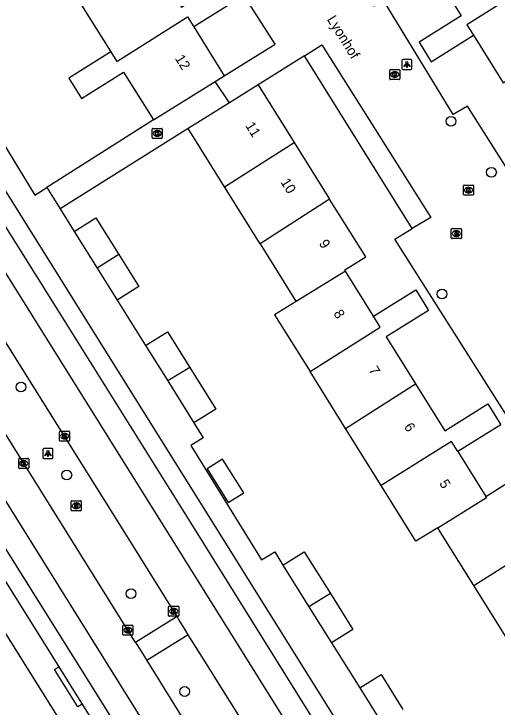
# Model space of a CAD drawing. Extents: x 158461 to 159795, y 387220 to 388672.
# Drawn here: x 158840 to 158888.2, y 387898.2 to 387967.3 of the extents above; entities that cross this region are included whole.
import ezdxf

# ---------------------------------------------------------------- set-up
doc = ezdxf.new("R2010")
doc.units = 0
for name, color, linetype in [('IMGEO_Boom', 7, 'Continuous'), ('IMGEO_Brandkraan', 7, 'Continuous'), ('IMGEO_Kolk', 7, 'Continuous'), ('IMGEO_Lichtpunt', 7, 'Continuous'), ('IMGEO_Openbare_ruimte_label', 7, 'Continuous'), ('IMGEO_Pand', 7, 'Continuous'), ('IMGEO_Pand_nummerreeks', 7, 'Continuous'), ('IMGEO_Parkeervlak_open', 7, 'Continuous'), ('IMGEO_Rijbaan_lokaal_gesloten', 7, 'Continuous'), ('IMGEO_Rijbaan_lokaal_open', 7, 'Continuous'), ('IMGEO_Rioolput', 7, 'Continuous'), ('IMGEO_Voetpad_open', 7, 'Continuous')]:
    doc.layers.add(name, color=color, linetype=linetype)

msp = doc.modelspace()

# ---------------------------------------------------------------- linework, layer by layer
at = {"layer": 'IMGEO_Boom'}
for centre in [(158883.59, 387956.588), (158887.621, 387951.512), (158882.693, 387939.38), (158840.749, 387930.117), (158845.315, 387921.36), (158851.709, 387909.538), (158857.066, 387899.781)]:
    msp.add_circle(centre, 0.489, dxfattribs=at)
at = {"layer": 'IMGEO_Brandkraan'}
for p, q in [((158883.624, 387944.978), (158883.624, 387945.83)), ((158883.699, 387945.904), (158884.551, 387945.904)), ((158884.625, 387945.83), (158884.625, 387944.978)), ((158884.135, 387945.124), (158884.11, 387945.124)), ((158884.112, 387945.684), (158884.137, 387945.684)), ((158884.551, 387944.904), (158883.699, 387944.904))]:
    msp.add_line(p, q, dxfattribs=at)
for points in [[(158883.624, 387944.978), (158883.624, 387945.83)], [(158883.699, 387945.904), (158884.551, 387945.904)], [(158884.625, 387945.83), (158884.625, 387944.978)], [(158883.972, 387945.604), (158883.972, 387945.204), (158884.185, 387945.204)], [(158884.203, 387945.604), (158883.972, 387945.604)], [(158884.151, 387945.523), (158884.097, 387945.523), (158884.097, 387945.447)], [(158884.097, 387945.447), (158884.15, 387945.447)], [(158884.159, 387945.371), (158884.097, 387945.371), (158884.097, 387945.29)], [(158884.097, 387945.29), (158884.159, 387945.29)], [(158884.551, 387944.904), (158883.699, 387944.904)]]:
    msp.add_lwpolyline(points, dxfattribs=at)
for centre, radius, start, end in [((158883.701, 387945.828), 0.0765, 91.55205, 178.44795), ((158883.701, 387945.828), 0.0765, 91.55205, 178.44795), ((158884.549, 387945.828), 0.0765, 1.55205, 88.44795), ((158884.549, 387945.828), 0.0765, 1.55205, 88.44795), ((158884.152, 387945.485), 0.0379, 267.82845, 90.93552), ((158884.16, 387945.33), 0.0404, 269.87594, 90.50774), ((158884.191, 387945.455), 0.251, 268.66757, 293.53466), ((158884.207, 387945.459), 0.145, 59.4692, 91.53667), ((158884.232, 387945.506), 0.0922, 285.51372, 58.15012), ((158884.237, 387945.314), 0.105, 301.31148, 78.98903), ((158883.701, 387944.98), 0.0765, 181.55205, 268.44795), ((158883.701, 387944.98), 0.0765, 181.55205, 268.44795), ((158884.549, 387944.98), 0.0765, 271.55205, 358.44795), ((158884.549, 387944.98), 0.0765, 271.55205, 358.44795)]:
    msp.add_arc(centre, radius, start, end, dxfattribs=at)
for centre, major_axis, ratio, start_param, end_param in [((158884.111, 387945.404), (-0.387, 0.002), 0.722429, 4.712389, 7.853982), ((158884.136, 387945.404), (-0.39, 0.002), 0.717154, 1.570796, 4.712389)]:
    msp.add_ellipse(centre, major_axis=major_axis, ratio=ratio, start_param=start_param, end_param=end_param, dxfattribs=at)
at = {"layer": 'IMGEO_Kolk'}
for p, q in [((158877.492, 387960.822), (158877.492, 387961.674)), ((158877.567, 387961.748), (158878.419, 387961.748)), ((158878.493, 387961.674), (158878.493, 387960.822)), ((158878.003, 387960.968), (158877.978, 387960.968)), ((158877.98, 387961.528), (158878.005, 387961.528)), ((158878.419, 387960.748), (158877.567, 387960.748)), ((158853.829, 387954.962), (158853.829, 387955.814)), ((158853.904, 387955.888), (158854.756, 387955.888)), ((158854.317, 387955.668), (158854.342, 387955.668)), ((158854.83, 387955.814), (158854.83, 387954.962)), ((158854.756, 387954.888), (158853.904, 387954.888)), ((158854.34, 387955.108), (158854.315, 387955.108)), ((158884.836, 387949.308), (158884.836, 387950.16)), ((158884.911, 387950.234), (158885.763, 387950.234)), ((158885.324, 387950.014), (158885.349, 387950.014)), ((158885.837, 387950.16), (158885.837, 387949.308)), ((158885.763, 387949.234), (158884.911, 387949.234)), ((158885.347, 387949.454), (158885.322, 387949.454)), ((158844.671, 387925.722), (158845.523, 387925.722)), ((158844.596, 387924.796), (158844.596, 387925.648)), ((158845.084, 387925.502), (158845.109, 387925.502)), ((158845.597, 387925.648), (158845.597, 387924.796)), ((158845.523, 387924.722), (158844.671, 387924.722)), ((158845.107, 387924.942), (158845.082, 387924.942)), ((158840.526, 387922.08), (158840.526, 387922.932)), ((158840.601, 387923.006), (158841.453, 387923.006)), ((158841.527, 387922.932), (158841.527, 387922.08)), ((158841.014, 387922.786), (158841.039, 387922.786)), ((158841.453, 387922.006), (158840.601, 387922.006)), ((158841.037, 387922.226), (158841.012, 387922.226)), ((158855.462, 387907.351), (158855.462, 387908.203)), ((158855.537, 387908.277), (158856.389, 387908.277)), ((158855.95, 387908.057), (158855.975, 387908.057)), ((158856.463, 387908.203), (158856.463, 387907.351)), ((158856.389, 387907.277), (158855.537, 387907.277)), ((158855.973, 387907.497), (158855.948, 387907.497)), ((158850.984, 387906.394), (158851.836, 387906.394)), ((158850.909, 387905.468), (158850.909, 387906.32)), ((158851.397, 387906.174), (158851.422, 387906.174)), ((158851.91, 387906.32), (158851.91, 387905.468)), ((158851.836, 387905.394), (158850.984, 387905.394)), ((158851.42, 387905.614), (158851.395, 387905.614))]:
    msp.add_line(p, q, dxfattribs=at)
for points in [[(158877.492, 387960.822), (158877.492, 387961.674)], [(158877.567, 387961.748), (158878.419, 387961.748)], [(158878.493, 387961.674), (158878.493, 387960.822)], [(158877.813, 387961.448), (158877.936, 387961.448), (158877.936, 387961.297), (158878.066, 387961.448), (158878.23, 387961.448), (158878.084, 387961.297), (158878.237, 387961.048), (158878.085, 387961.048), (158878, 387961.212), (158877.936, 387961.145), (158877.936, 387961.048), (158877.813, 387961.048), (158877.813, 387961.448)], [(158878.419, 387960.748), (158877.567, 387960.748)], [(158853.829, 387954.962), (158853.829, 387955.814)], [(158853.904, 387955.888), (158854.756, 387955.888)], [(158854.15, 387955.588), (158854.273, 387955.588), (158854.273, 387955.437), (158854.403, 387955.588), (158854.567, 387955.588), (158854.421, 387955.437), (158854.574, 387955.188), (158854.422, 387955.188), (158854.337, 387955.352), (158854.273, 387955.285), (158854.273, 387955.188), (158854.15, 387955.188), (158854.15, 387955.588)], [(158854.83, 387955.814), (158854.83, 387954.962)], [(158854.756, 387954.888), (158853.904, 387954.888)], [(158884.836, 387949.308), (158884.836, 387950.16)], [(158884.911, 387950.234), (158885.763, 387950.234)], [(158885.157, 387949.934), (158885.28, 387949.934), (158885.28, 387949.783), (158885.41, 387949.934), (158885.574, 387949.934), (158885.428, 387949.783), (158885.581, 387949.534), (158885.429, 387949.534), (158885.344, 387949.698), (158885.28, 387949.631), (158885.28, 387949.534), (158885.157, 387949.534), (158885.157, 387949.934)], [(158885.837, 387950.16), (158885.837, 387949.308)], [(158885.763, 387949.234), (158884.911, 387949.234)], [(158844.671, 387925.722), (158845.523, 387925.722)], [(158844.596, 387924.796), (158844.596, 387925.648)], [(158844.917, 387925.422), (158845.04, 387925.422), (158845.04, 387925.271), (158845.17, 387925.422), (158845.334, 387925.422), (158845.188, 387925.271), (158845.341, 387925.022), (158845.189, 387925.022), (158845.104, 387925.186), (158845.04, 387925.119), (158845.04, 387925.022), (158844.917, 387925.022), (158844.917, 387925.422)], [(158845.597, 387925.648), (158845.597, 387924.796)], [(158845.523, 387924.722), (158844.671, 387924.722)], [(158840.526, 387922.08), (158840.526, 387922.932)], [(158840.601, 387923.006), (158841.453, 387923.006)], [(158841.527, 387922.932), (158841.527, 387922.08)], [(158840.847, 387922.706), (158840.97, 387922.706), (158840.97, 387922.555), (158841.1, 387922.706), (158841.264, 387922.706), (158841.118, 387922.555), (158841.271, 387922.306), (158841.119, 387922.306), (158841.034, 387922.47), (158840.97, 387922.403), (158840.97, 387922.306), (158840.847, 387922.306), (158840.847, 387922.706)], [(158841.453, 387922.006), (158840.601, 387922.006)], [(158855.462, 387907.351), (158855.462, 387908.203)], [(158855.537, 387908.277), (158856.389, 387908.277)], [(158855.783, 387907.977), (158855.906, 387907.977), (158855.906, 387907.826), (158856.036, 387907.977), (158856.2, 387907.977), (158856.054, 387907.826), (158856.207, 387907.577), (158856.055, 387907.577), (158855.97, 387907.741), (158855.906, 387907.674), (158855.906, 387907.577), (158855.783, 387907.577), (158855.783, 387907.977)], [(158856.463, 387908.203), (158856.463, 387907.351)], [(158856.389, 387907.277), (158855.537, 387907.277)], [(158850.984, 387906.394), (158851.836, 387906.394)], [(158850.909, 387905.468), (158850.909, 387906.32)], [(158851.23, 387906.094), (158851.353, 387906.094), (158851.353, 387905.943), (158851.483, 387906.094), (158851.647, 387906.094), (158851.501, 387905.943), (158851.654, 387905.694), (158851.502, 387905.694), (158851.417, 387905.858), (158851.353, 387905.791), (158851.353, 387905.694), (158851.23, 387905.694), (158851.23, 387906.094)], [(158851.91, 387906.32), (158851.91, 387905.468)], [(158851.836, 387905.394), (158850.984, 387905.394)]]:
    msp.add_lwpolyline(points, dxfattribs=at)
for centre, start, end in [((158877.569, 387961.672), 91.55205, 178.44795), ((158877.569, 387961.672), 91.55205, 178.44795), ((158878.417, 387961.672), 1.55205, 88.44795), ((158878.417, 387961.672), 1.55205, 88.44795), ((158877.569, 387960.824), 181.55205, 268.44795), ((158877.569, 387960.824), 181.55205, 268.44795), ((158878.417, 387960.824), 271.55205, 358.44795), ((158878.417, 387960.824), 271.55205, 358.44795), ((158853.906, 387955.812), 91.55205, 178.44795), ((158853.906, 387955.812), 91.55205, 178.44795), ((158854.754, 387955.812), 1.55205, 88.44795), ((158854.754, 387955.812), 1.55205, 88.44795), ((158853.906, 387954.964), 181.55205, 268.44795), ((158853.906, 387954.964), 181.55205, 268.44795), ((158854.754, 387954.964), 271.55205, 358.44795), ((158854.754, 387954.964), 271.55205, 358.44795), ((158884.913, 387950.158), 91.55205, 178.44795), ((158884.913, 387950.158), 91.55205, 178.44795), ((158885.761, 387950.158), 1.55205, 88.44795), ((158885.761, 387950.158), 1.55205, 88.44795), ((158884.913, 387949.31), 181.55205, 268.44795), ((158884.913, 387949.31), 181.55205, 268.44795), ((158885.761, 387949.31), 271.55205, 358.44795), ((158885.761, 387949.31), 271.55205, 358.44795), ((158844.673, 387925.646), 91.55205, 178.44795), ((158844.673, 387925.646), 91.55205, 178.44795), ((158845.521, 387925.646), 1.55205, 88.44795), ((158845.521, 387925.646), 1.55205, 88.44795), ((158844.673, 387924.798), 181.55205, 268.44795), ((158844.673, 387924.798), 181.55205, 268.44795), ((158845.521, 387924.798), 271.55205, 358.44795), ((158845.521, 387924.798), 271.55205, 358.44795), ((158840.603, 387922.93), 91.55205, 178.44795), ((158840.603, 387922.93), 91.55205, 178.44795), ((158841.451, 387922.93), 1.55205, 88.44795), ((158841.451, 387922.93), 1.55205, 88.44795), ((158840.603, 387922.082), 181.55205, 268.44795), ((158840.603, 387922.082), 181.55205, 268.44795), ((158841.451, 387922.082), 271.55205, 358.44795), ((158841.451, 387922.082), 271.55205, 358.44795), ((158855.539, 387908.201), 91.55205, 178.44795), ((158855.539, 387908.201), 91.55205, 178.44795), ((158856.387, 387908.201), 1.55205, 88.44795), ((158856.387, 387908.201), 1.55205, 88.44795), ((158855.539, 387907.353), 181.55205, 268.44795), ((158855.539, 387907.353), 181.55205, 268.44795), ((158856.387, 387907.353), 271.55205, 358.44795), ((158856.387, 387907.353), 271.55205, 358.44795), ((158850.986, 387906.318), 91.55205, 178.44795), ((158850.986, 387906.318), 91.55205, 178.44795), ((158851.834, 387906.318), 1.55205, 88.44795), ((158851.834, 387906.318), 1.55205, 88.44795), ((158850.986, 387905.47), 181.55205, 268.44795), ((158850.986, 387905.47), 181.55205, 268.44795), ((158851.834, 387905.47), 271.55205, 358.44795), ((158851.834, 387905.47), 271.55205, 358.44795)]:
    msp.add_arc(centre, 0.0765, start, end, dxfattribs=at)
for centre, major_axis, ratio, start_param, end_param in [((158877.979, 387961.248), (-0.387, 0.002), 0.722429, 4.712389, 7.853982), ((158878.004, 387961.248), (-0.39, 0.002), 0.717154, 1.570796, 4.712389), ((158854.316, 387955.388), (-0.387, 0.002), 0.722429, 4.712389, 7.853982), ((158854.341, 387955.388), (-0.39, 0.002), 0.717154, 1.570796, 4.712389), ((158885.323, 387949.734), (-0.387, 0.002), 0.722429, 4.712389, 7.853982), ((158885.348, 387949.734), (-0.39, 0.002), 0.717154, 1.570796, 4.712389), ((158845.083, 387925.222), (-0.387, 0.002), 0.722429, 4.712389, 7.853982), ((158845.108, 387925.222), (-0.39, 0.002), 0.717154, 1.570796, 4.712389), ((158841.013, 387922.506), (-0.387, 0.002), 0.722429, 4.712389, 7.853982), ((158841.038, 387922.506), (-0.39, 0.002), 0.717154, 1.570796, 4.712389), ((158855.949, 387907.777), (-0.387, 0.002), 0.722429, 4.712389, 7.853982), ((158855.974, 387907.777), (-0.39, 0.002), 0.717154, 1.570796, 4.712389), ((158851.396, 387905.894), (-0.387, 0.002), 0.722429, 4.712389, 7.853982), ((158851.421, 387905.894), (-0.39, 0.002), 0.717154, 1.570796, 4.712389)]:
    msp.add_ellipse(centre, major_axis=major_axis, ratio=ratio, start_param=start_param, end_param=end_param, dxfattribs=at)
at = {"layer": 'IMGEO_Lichtpunt'}
for p, q in [((158878.704, 387962.663), (158878.704, 387961.856)), ((158878.704, 387962.663), (158878.704, 387961.856)), ((158879.606, 387962.758), (158878.798, 387962.758)), ((158879.606, 387962.758), (158878.798, 387962.758)), ((158879.7, 387961.856), (158879.7, 387962.663)), ((158879.7, 387961.856), (158879.7, 387962.663)), ((158878.798, 387961.762), (158879.606, 387961.762)), ((158878.798, 387961.762), (158879.606, 387961.762)), ((158842.944, 387923.902), (158842.944, 387923.095)), ((158842.944, 387923.902), (158842.944, 387923.095)), ((158843.846, 387923.997), (158843.038, 387923.997)), ((158843.846, 387923.997), (158843.038, 387923.997)), ((158843.94, 387923.095), (158843.94, 387923.902)), ((158843.94, 387923.095), (158843.94, 387923.902)), ((158843.038, 387923.001), (158843.846, 387923.001)), ((158843.038, 387923.001), (158843.846, 387923.001))]:
    msp.add_line(p, q, dxfattribs=at)
for points in [[(158879.078, 387962.327), (158879.117, 387962.299), (158878.929, 387962.037), (158878.891, 387962.064), (158879.078, 387962.327)], [(158879.29, 387962.299), (158879.328, 387962.326), (158879.515, 387962.064), (158879.476, 387962.036), (158879.29, 387962.299)], [(158879.18, 387962.279), (158879.227, 387962.279), (158879.227, 387961.957), (158879.18, 387961.957), (158879.18, 387962.279)], [(158843.318, 387923.566), (158843.357, 387923.538), (158843.169, 387923.276), (158843.131, 387923.303), (158843.318, 387923.566)], [(158843.42, 387923.518), (158843.467, 387923.518), (158843.467, 387923.196), (158843.42, 387923.196), (158843.42, 387923.518)], [(158843.53, 387923.538), (158843.568, 387923.565), (158843.755, 387923.303), (158843.716, 387923.275), (158843.53, 387923.538)]]:
    msp.add_lwpolyline(points, dxfattribs=at)
for centre in [(158879.203, 387962.461), (158843.443, 387923.7)]:
    msp.add_circle(centre, 0.0994, dxfattribs=at)
for centre, start, end in [((158878.798, 387962.663), 90, 180), ((158878.798, 387962.663), 90, 180), ((158879.606, 387962.663), 0, 90), ((158879.606, 387962.663), 0, 90), ((158878.798, 387961.856), 180, 270), ((158878.798, 387961.856), 180, 270), ((158879.606, 387961.856), 270, 0), ((158879.606, 387961.856), 270, 360), ((158843.038, 387923.902), 90, 180), ((158843.038, 387923.902), 90, 180), ((158843.846, 387923.902), 0, 90), ((158843.846, 387923.902), 0, 90), ((158843.038, 387923.095), 180, 270), ((158843.038, 387923.095), 180, 270), ((158843.846, 387923.095), 270, 0), ((158843.846, 387923.095), 270, 360)]:
    msp.add_arc(centre, 0.0946, start, end, dxfattribs=at)
at = {"layer": 'IMGEO_Pand'}
for points in [[(158853.846, 387972.559), (158856.735, 387967.949), (158860.892, 387970.548), (158862.108, 387968.603), (158857.96, 387966.01)], [(158881.749, 387971.701), (158884.606, 387967.09), (158880.416, 387964.459), (158881.627, 387962.531), (158885.822, 387965.165)], [(158892.208, 387970.653), (158885.167, 387966.2), (158885.822, 387965.165)], [(158846.777, 387968.156), (158849.689, 387963.501)], [(158849.689, 387963.501), (158850.309, 387962.537), (158857.334, 387966.995), (158857.96, 387966.01)], [(158857.96, 387966.01), (158861.007, 387961.124)], [(158885.822, 387965.165), (158888.8, 387960.424), (158889.039, 387960.579)], [(158849.689, 387963.501), (158845.515, 387960.893), (158846.775, 387958.876), (158850.974, 387961.5), (158853.96, 387956.721)], [(158860.093, 387960.553), (158861.007, 387961.124)], [(158853.96, 387956.721), (158860.093, 387960.553)], [(158864.39, 387960.231), (158861.516, 387958.435)], [(158864.39, 387960.231), (158867.978, 387954.489)], [(158861.516, 387958.435), (158857.396, 387955.86)], [(158861.026, 387950.052), (158857.396, 387955.86)], [(158861.026, 387950.052), (158867.978, 387954.489)], [(158867.978, 387954.489), (158871.502, 387948.849)], [(158864.577, 387944.369), (158861.026, 387950.052)], [(158871.502, 387948.849), (158864.577, 387944.369)], [(158873.082, 387941.676), (158873.02, 387941.777), (158875.107, 387943.081), (158871.502, 387948.849)], [(158846.058, 387945.62), (158848.222, 387946.973), (158850.498, 387943.332)], [(158846.058, 387945.62), (158848.346, 387941.959)], [(158864.577, 387944.369), (158868.066, 387938.786), (158868.163, 387938.63)], [(158850.498, 387943.332), (158848.346, 387941.959)], [(158850.498, 387943.332), (158852.507, 387940.118), (158850.342, 387938.765)], [(158848.346, 387941.959), (158850.342, 387938.765)], [(158873.082, 387941.676), (158868.163, 387938.63)], [(158875.869, 387937.162), (158873.082, 387941.676)], [(158875.869, 387937.162), (158880.075, 387939.791), (158881.349, 387937.752), (158877.132, 387935.117), (158880.056, 387930.434)], [(158868.163, 387938.63), (158866.017, 387937.301), (158869.549, 387931.649)], [(158869.549, 387931.649), (158876.524, 387936.097), (158875.869, 387937.162)], [(158853.175, 387934.262), (158855.343, 387935.617), (158857.563, 387932.066)], [(158853.175, 387934.262), (158855.389, 387930.719)], [(158857.563, 387932.066), (158855.389, 387930.719)], [(158857.563, 387932.066), (158860.157, 387927.915), (158857.988, 387926.56)], [(158873.089, 387925.984), (158869.549, 387931.649)], [(158855.389, 387930.719), (158857.988, 387926.56)], [(158873.089, 387925.984), (158880.056, 387930.434)], [(158880.056, 387930.434), (158882.975, 387925.758), (158887.265, 387928.439), (158888.561, 387926.366), (158884.269, 387923.684)], [(158876.634, 387920.312), (158873.089, 387925.984)], [(158884.269, 387923.684), (158883.637, 387924.697), (158876.634, 387920.312)], [(158884.269, 387923.684), (158887.068, 387919.204)], [(158859.294, 387921.979), (158861.394, 387918.617), (158862.941, 387919.584), (158860.841, 387922.945), (158859.294, 387921.979)], [(158882.265, 387916.1), (158880.098, 387914.769), (158876.634, 387920.312)], [(158887.068, 387919.204), (158889.231, 387920.556), (158892.851, 387914.764)], [(158882.265, 387916.1), (158887.139, 387919.095), (158887.068, 387919.204)], [(158885.87, 387910.33), (158882.412, 387915.865), (158882.265, 387916.1)], [(158885.87, 387910.33), (158892.851, 387914.764)], [(158866.856, 387912.361), (158868.979, 387913.689), (158871.576, 387909.533)], [(158866.856, 387912.361), (158869.443, 387908.222)], [(158889.404, 387904.673), (158885.87, 387910.33)], [(158871.576, 387909.533), (158869.443, 387908.222)], [(158871.576, 387909.533), (158873.812, 387905.955), (158871.689, 387904.628)], [(158869.443, 387908.222), (158871.689, 387904.628)], [(158874.508, 387900.137), (158876.627, 387901.461), (158878.804, 387897.977)], [(158874.508, 387900.137), (158876.692, 387896.643)]]:
    msp.add_lwpolyline(points, dxfattribs=at)
at = {"layer": 'IMGEO_Parkeervlak_open'}
msp.add_lwpolyline([(158879.708, 387945.914), (158869.001, 387963.121)], dxfattribs=at)
at = {"layer": 'IMGEO_Rijbaan_lokaal_gesloten'}
for points in [[(158777.679, 388039.896), (158792.31, 388017.418), (158834.227, 387949.391), (158871.964, 387889.05), (158887.922, 387863.502)], [(158774.869, 388017.05), (158778.332, 388014.385), (158779.563, 388013.342), (158780.694, 388012.384), (158785.095, 388005.301), (158793.995, 387991.082), (158802.455, 387977.515), (158810.737, 387964.275), (158822.801, 387944.946), (158836.678, 387922.775), (158853.754, 387895.444), (158877.701, 387857.148)], [(158860.281, 387880.424), (158855.269, 387888.326), (158848.058, 387899.934), (158837.312, 387917.021), (158827.094, 387933.478), (158816.677, 387949.935), (158806.829, 387965.972), (158797.5, 387980.78), (158793.285, 387987.639), (158789.331, 387993.838), (158785.494, 388000), (158780.215, 388008.468)], [(158856.298, 387907.238), (158851.263, 387915.352), (158842.383, 387929.569), (158816.975, 387970.262), (158811.283, 387979.426)], [(158852.17, 387904.676), (158837.096, 387928.793), (158824.322, 387949.219), (158812.237, 387968.597), (158807.11, 387976.831)], [(158879.01, 387882.568), (158877.715, 387884.504), (158870.764, 387895.592), (158857.71, 387916.557), (158844.256, 387938.083), (158828.405, 387963.308), (158826.242, 387967.003)], [(158857.412, 387905.443), (158857.076, 387905.984), (158856.412, 387907.055), (158856.298, 387907.238)], [(158866.508, 387890.905), (158858.993, 387902.895), (158857.412, 387905.443)], [(158852.17, 387904.676), (158852.297, 387904.473), (158852.923, 387903.465), (158853.284, 387902.882)], [(158853.284, 387902.882), (158861.396, 387889.771), (158862.321, 387888.279)]]:
    msp.add_lwpolyline(points, dxfattribs=at)
at = {"layer": 'IMGEO_Rijbaan_lokaal_open'}
for points in [[(158905.268, 387923.321), (158897.893, 387934.619), (158899.452, 387935.658), (158885.25, 387958.082), (158883.811, 387957.283), (158876.889, 387968.591), (158875.929, 387968.062), (158866.631, 387982.909), (158867.51, 387983.388), (158862.418, 387991.592)], [(158861.007, 387961.124), (158866.063, 387964.292), (158851.73, 387986.727)], [(158869.001, 387963.121), (158870.739, 387964.196), (158881.568, 387947.018), (158879.708, 387945.914)], [(158869.001, 387963.121), (158864.39, 387960.231)], [(158861.516, 387958.435), (158860.093, 387960.553)], [(158892.352, 387922.241), (158878.009, 387944.836), (158879.708, 387945.914)]]:
    msp.add_lwpolyline(points, dxfattribs=at)
at = {"layer": 'IMGEO_Rioolput'}
for p, q in [((158845.832, 387918.788), (158846.684, 387918.788)), ((158845.757, 387917.862), (158845.757, 387918.714)), ((158846.245, 387918.568), (158846.27, 387918.568)), ((158846.758, 387918.714), (158846.758, 387917.862)), ((158846.684, 387917.788), (158845.832, 387917.788)), ((158846.268, 387918.008), (158846.243, 387918.008))]:
    msp.add_line(p, q, dxfattribs=at)
for points in [[(158845.832, 387918.788), (158846.684, 387918.788)], [(158845.757, 387917.862), (158845.757, 387918.714)], [(158846.346, 387918.486), (158846.094, 387918.488), (158846.094, 387918.088)], [(158846.094, 387918.088), (158846.218, 387918.088), (158846.218, 387918.25), (158846.229, 387918.25)], [(158846.272, 387918.407), (158846.218, 387918.407), (158846.218, 387918.326)], [(158846.218, 387918.326), (158846.27, 387918.326)], [(158846.276, 387918.221), (158846.347, 387918.088), (158846.487, 387918.088), (158846.422, 387918.214)], [(158846.758, 387918.714), (158846.758, 387917.862)], [(158846.684, 387917.788), (158845.832, 387917.788)]]:
    msp.add_lwpolyline(points, dxfattribs=at)
for centre, radius, start, end in [((158845.834, 387918.712), 0.0765, 91.55205, 178.44795), ((158845.834, 387918.712), 0.0765, 91.55205, 178.44795), ((158846.682, 387918.712), 0.0765, 1.55205, 88.44795), ((158846.682, 387918.712), 0.0765, 1.55205, 88.44795), ((158846.228, 387918.197), 0.0533, 26.02933, 88.69889), ((158846.254, 387918.515), 0.19, 274.7715, 282.96867), ((158846.278, 387918.311), 0.0964, 77.00612, 93.18647), ((158846.292, 387918.368), 0.0378, 276.66336, 79.67722), ((158846.345, 387918.376), 0.109, 350.36119, 89.41601), ((158846.343, 387918.376), 0.112, 277.58423, 350.98172), ((158846.327, 387918.161), 0.108, 29.51342, 73.79051), ((158845.834, 387917.864), 0.0765, 181.55205, 268.44795), ((158845.834, 387917.864), 0.0765, 181.55205, 268.44795), ((158846.682, 387917.864), 0.0765, 271.55205, 358.44795), ((158846.682, 387917.864), 0.0765, 271.55205, 358.44795)]:
    msp.add_arc(centre, radius, start, end, dxfattribs=at)
for centre, major_axis, ratio, start_param, end_param in [((158846.244, 387918.288), (-0.387, 0.002), 0.722429, 4.712389, 7.853982), ((158846.269, 387918.288), (-0.39, 0.002), 0.717154, 1.570796, 4.712389)]:
    msp.add_ellipse(centre, major_axis=major_axis, ratio=ratio, start_param=start_param, end_param=end_param, dxfattribs=at)
at = {"layer": 'IMGEO_Voetpad_open'}
for points in [[(158751.855, 388042.396), (158752.718, 388041.901), (158753.29, 388041.304), (158790.47, 387981.392), (158792.305, 387978.478), (158793.275, 387978.973), (158854.735, 387880.753)], [(158780.136, 388004.918), (158781.104, 388003.382), (158783.303, 388000), (158798.109, 387976.516), (158844.522, 387902.25)], [(158827.359, 387975.532), (158826.221, 387974.793), (158831.334, 387966.514), (158835.07, 387960.815), (158842.141, 387949.248), (158843.316, 387949.991)], [(158879.11, 387885.808), (158829.151, 387965.739)], [(158853.96, 387956.721), (158843.316, 387949.991)], [(158857.396, 387955.86), (158844.659, 387947.867)], [(158843.316, 387949.991), (158844.659, 387947.867)], [(158844.659, 387947.867), (158846.058, 387945.62)], [(158850.342, 387938.765), (158853.175, 387934.262)], [(158857.988, 387926.56), (158858.892, 387925.071), (158857.682, 387924.302), (158864.703, 387912.884), (158866.053, 387913.683), (158866.856, 387912.361)], [(158856.298, 387907.238), (158852.17, 387904.676)], [(158857.412, 387905.443), (158853.284, 387902.882)], [(158871.689, 387904.628), (158874.508, 387900.137)], [(158846.848, 387898.516), (158846.424, 387898.252), (158844.098, 387901.986), (158844.522, 387902.25)], [(158844.522, 387902.25), (158846.16, 387899.629), (158846.848, 387898.516)], [(158846.848, 387898.516), (158857.012, 387882.068)]]:
    msp.add_lwpolyline(points, dxfattribs=at)

# ---------------------------------------------------------------- texts
at = {"layer": 'IMGEO_Openbare_ruimte_label'}
msp.add_text('Lyonhof', height=1, rotation=301.87782, dxfattribs=at).set_placement((158871.198, 387966.744))
at = {"layer": 'IMGEO_Pand_nummerreeks'}
for s, rotation, p in [('12', 302.01171, (158856.055, 387962.857)), ('11', 302.00118, (158863.066, 387956.161)), ('10', 302.00118, (158866.579, 387950.538)), ('9', 301.99948, (158870.394, 387944.435)), ('8', 301.89635, (158871.848, 387937.453)), ('7', 301.89551, (158875.358, 387931.813)), ('6', 301.89551, (158878.87, 387926.17)), ('5', 301.89635, (158882.382, 387920.526))]:
    msp.add_text(s, height=1, rotation=rotation, dxfattribs=at).set_placement(p)

doc.saveas('drawing.dxf')
